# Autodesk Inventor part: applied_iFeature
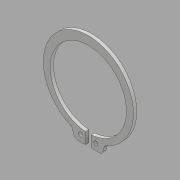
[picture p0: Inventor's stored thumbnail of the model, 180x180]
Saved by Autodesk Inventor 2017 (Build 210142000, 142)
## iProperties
Created: 2016-06
Part Number: applied_iFeature
Material: Generic
Document SubType Name: Modeling
Designer: CADCIM
Density: 1 g/cm^3
Appearance: Default
Author: CADCIM
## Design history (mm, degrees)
sketch "Sketch1"
  geometry: L1 (9.52, -25.305)-(8.665, -28.284); L2 (6.743, -29.733)-(1.75, -29.733); L3 (1.75, -29.733)-(1.75, -22.833); L4 (0, 0)-(0, -33.55); L5 (-6.743, -29.733)-(-1.75, -29.733); L6 (-1.75, -29.733)-(-1.75, -22.833); L7 (-9.52, -25.305)-(-8.665, -28.284); C1 r 1.25 at (4.55, -25.815); C2 r 1.25 at (-4.55, -25.815); A1 r 22.9 centre (0, 0) between (1.75, -22.833) and (-1.75, -22.833); A2 r 27.1 centre (0, 0.9) between (10.656, -24.017) and (-10.656, -24.017); A3 r 2 centre (-6.743, -27.733) between (-8.665, -28.284) and (-6.743, -29.733); A4 r 2 centre (-11.442, -25.856) between (-9.52, -25.305) and (-10.656, -24.017); A5 r 2 centre (11.442, -25.856) between (10.656, -24.017) and (9.52, -25.305); A6 r 2 centre (6.743, -27.733) between (6.743, -29.733) and (8.665, -28.284); 12 further points
  constraints: 18 point on circle, 14 end point, 8 centre point, 8 point on line, 8 tangent, 4 equal radius, 4 symmetric about line, 2 coincident, 2 midpoint, 1 horizontal, 1 horizontal alignment, 1 perpendicular, 1 vertical
  dimensions: "d0" = 45.8 diameter of A1; "d4" = 6.9 distance from line of L6.end L5; "d5" = 5.1 distance of point (0, 28) point (0, 22.9); "d6" = 2.5 diameter of C1; "d8" = 2 radius of A3 (derived); "d9" = 2.8 distance from line of C1.centre L3; "d10" = 3.5 distance of L5.end L2.end; "d11" = 27.1 radius of A2; "d14" = 6.5 distance of L5.end point (-8.25, -29.733); "d15" = 32 deg angle of L7 L1
extrude "Extrusion1" new body sketch "Sketch1" distance "d16" = 2; taper "d17" = 0 deg
body "Solid1"
